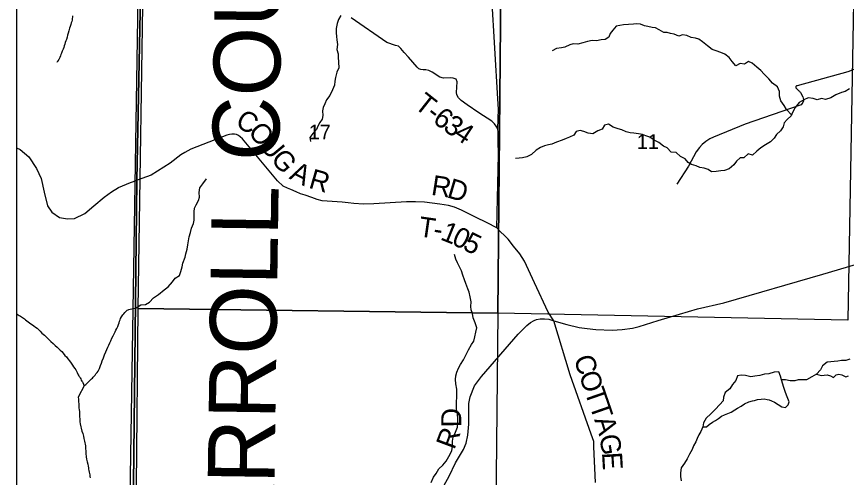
# Model space of a CAD drawing. Extents: x -1.2 to 34, y -8.5 to 22.
# Drawn here: x 2.1 to 4.454, y 18.225 to 19.531 of the extents above; entities that cross this region are included whole.
import ezdxf

# ---------------------------------------------------------------- set-up
doc = ezdxf.new("R2010")
doc.units = 0
for name, color, linetype in [('DV_X_County_Line', 7, 'Continuous'), ('GM_X_County_Road', 7, 'Continuous'), ('GM_X_County_Road_Text', 7, 'Continuous'), ('GM_X_County_Text', 7, 'Continuous'), ('GM_X_Minor_Lake', 7, 'Continuous'), ('GM_X_Minor_River', 7, 'Continuous'), ('GM_X_Section', 7, 'Continuous'), ('GM_X_Section_Text', 7, 'Continuous'), ('GM_X_Township_Road', 7, 'Continuous'), ('GM_X_Township_Road_Text', 7, 'Continuous'), ('GM_X_Unincorporated_Text', 7, 'Continuous'), ('SH_Cut_Line', 7, 'Continuous'), ('SH_Data', 7, 'Continuous')]:
    doc.layers.add(name, color=color, linetype=linetype)

msp = doc.modelspace()

# ---------------------------------------------------------------- linework, layer by layer
at = {"layer": 'DV_X_County_Line'}
msp.add_line((2.3586, 14.1), (2.465, 20.9), dxfattribs=at)
at = {"layer": 'GM_X_County_Road'}
msp.add_lwpolyline([(3.2928, 18.1676), (3.3265, 18.2291), (3.3449, 18.2664), (3.3677, 18.3046), (3.3748, 18.3225), (3.38, 18.3454), (3.3828, 18.3766), (3.3828, 18.4351), (3.3868, 18.4541), (3.3991, 18.485), (3.4183, 18.5117), (3.5231, 18.6316), (3.5436, 18.6524), (3.5469, 18.6554), (3.5577, 18.6643), (3.5681, 18.6701), (3.575, 18.6729), (3.5854, 18.6751), (3.5974, 18.6751), (3.6098, 18.6738), (3.6237, 18.6695), (3.6608, 18.6582), (3.6955, 18.6501), (3.7185, 18.6469), (3.743, 18.6441), (3.7888, 18.6427), (3.8178, 18.6443), (3.8473, 18.6482), (3.8658, 18.6531), (3.9197, 18.6699), (3.98, 18.6882), (4.0313, 18.7027), (4.1057, 18.7202), (4.3866, 18.8016), (4.7601, 18.9122)], dxfattribs=at)
at = {"layer": 'GM_X_Minor_Lake'}
for points in [[(4.463, 18.5606), (4.4524, 18.5571), (4.4395, 18.5562), (4.4293, 18.5546), (4.4187, 18.5541), (4.4092, 18.5533), (4.3989, 18.5517), (4.3861, 18.5417), (4.3801, 18.5299), (4.3684, 18.5184)], [(4.2698, 18.5016), (4.2667, 18.5118), (4.262, 18.5243), (4.2488, 18.5234), (4.234, 18.5188), (4.2218, 18.5179), (4.2082, 18.5144), (4.1938, 18.512), (4.1824, 18.51), (4.1672, 18.514), (4.1554, 18.5154), (4.1452, 18.5131), (4.1396, 18.4997), (4.1302, 18.489), (4.1227, 18.4768), (4.1102, 18.4664), (4.1054, 18.4527), (4.104, 18.4428), (4.0949, 18.4318), (4.0818, 18.418), (4.069, 18.4053), (4.0562, 18.3931), (4.0479, 18.3801), (4.0469, 18.3683)], [(4.0469, 18.3683), (4.0571, 18.3684), (4.0647, 18.3753), (4.0737, 18.3818), (4.0824, 18.3868), (4.0907, 18.3926), (4.0998, 18.3991), (4.1081, 18.403), (4.1176, 18.4061), (4.127, 18.4104), (4.1369, 18.4169), (4.1452, 18.4212), (4.155, 18.427), (4.1648, 18.4339), (4.1773, 18.4397), (4.1872, 18.4428), (4.1928, 18.4436), (4.2019, 18.446), (4.2118, 18.4472), (4.2202, 18.4476), (4.2293, 18.4462), (4.235, 18.4451), (4.2411, 18.4425), (4.2495, 18.4388), (4.2605, 18.4324), (4.2709, 18.4257), (4.2811, 18.4231), (4.2887, 18.4308), (4.2916, 18.4395), (4.2878, 18.449), (4.2839, 18.4581), (4.28, 18.4687), (4.2761, 18.48), (4.2698, 18.5016)], [(4.3684, 18.5184), (4.3822, 18.514), (4.3905, 18.5152), (4.3992, 18.5164), (4.4084, 18.5134), (4.4175, 18.5082), (4.4247, 18.5158), (4.4323, 18.5182), (4.441, 18.5164), (4.4517, 18.5104), (4.46, 18.5135)]]:
    msp.add_lwpolyline(points, dxfattribs=at)
at = {"layer": 'GM_X_Minor_River'}
for points in [[(2.2587, 19.5334), (2.2584, 19.5296), (2.2577, 19.5254), (2.2573, 19.5213), (2.2563, 19.5174), (2.2552, 19.5133), (2.2537, 19.5087), (2.2519, 19.5033), (2.2501, 19.4984), (2.2483, 19.4904), (2.2461, 19.4843), (2.2446, 19.4786), (2.2432, 19.4725), (2.2414, 19.4664), (2.2395, 19.4622), (2.2381, 19.4576), (2.2366, 19.453), (2.2352, 19.4484), (2.2337, 19.4439), (2.2319, 19.4385), (2.2297, 19.4332), (2.2271, 19.4271), (2.2256, 19.4236), (2.2246, 19.4202), (2.2227, 19.4156), (2.2198, 19.4099), (2.2172, 19.4057), (2.2157, 19.403), (2.2149, 19.403), (2.2146, 19.4011)], [(3.0198, 19.5341), (3.0135, 19.5226), (3.0095, 19.5112), (3.0066, 19.4975), (3.0064, 19.4853), (3.0076, 19.4747), (3.0085, 19.4653), (3.0098, 19.4516), (3.0084, 19.4383), (3.012, 19.4259), (3.0121, 19.416)], [(4.2984, 19.2528), (4.2837, 19.268), (4.2772, 19.2793), (4.2676, 19.2925), (4.2637, 19.3054), (4.2643, 19.3187), (4.2581, 19.3323), (4.244, 19.3424), (4.2336, 19.3544), (4.2206, 19.3676), (4.2106, 19.3781), (4.1995, 19.3879), (4.1861, 19.3996), (4.1762, 19.404), (4.1649, 19.396), (4.1519, 19.3985), (4.1402, 19.3919), (4.1295, 19.4036), (4.1214, 19.4149), (4.1092, 19.4243), (4.0977, 19.4295), (4.0844, 19.4343), (4.0726, 19.4376), (4.06, 19.4482), (4.0454, 19.4598), (4.0355, 19.4669), (4.026, 19.4703), (4.0138, 19.4717), (4.0012, 19.478), (3.9887, 19.479), (3.9781, 19.4759), (3.9651, 19.4811), (3.9552, 19.4837), (3.9453, 19.4859), (3.9358, 19.4865), (3.9228, 19.494), (3.9121, 19.4992), (3.9023, 19.5003), (3.8905, 19.5032), (3.8806, 19.5054), (3.8695, 19.5095), (3.8596, 19.5109), (3.8501, 19.5097), (3.8357, 19.5084), (3.8217, 19.5079), (3.8107, 19.5059), (3.8008, 19.5036), (3.791, 19.4929), (3.7835, 19.4829), (3.7794, 19.473), (3.7692, 19.4661), (3.7578, 19.4656), (3.745, 19.4629), (3.7328, 19.4635), (3.7192, 19.4604), (3.7059, 19.4565), (3.6915, 19.4533), (3.6789, 19.4536), (3.6691, 19.4508), (3.6551, 19.4446), (3.6452, 19.443), (3.6312, 19.4403), (3.6191, 19.4345)], [(3.0121, 19.416), (3.0127, 19.4016), (3.0136, 19.3864), (3.0084, 19.3738), (3.0044, 19.3582), (3.0023, 19.3484), (3.0017, 19.3373), (2.9958, 19.3236), (2.9884, 19.308), (2.9791, 19.295), (2.9743, 19.2843), (2.9698, 19.274), (2.9677, 19.2641), (2.969, 19.2509), (2.9665, 19.2402), (2.9601, 19.2306), (2.9546, 19.2203), (2.9505, 19.2108), (2.9404, 19.1997), (2.9315, 19.189), (2.9339, 19.1772)], [(4.4629, 19.3264), (4.45, 19.3191)], [(4.45, 19.3191), (4.4402, 19.3156), (4.4239, 19.3098), (4.4099, 19.3009), (4.3948, 19.2966), (4.3826, 19.2988), (4.3705, 19.2953), (4.3591, 19.2986), (4.3454, 19.3008), (4.3329, 19.2957), (4.3193, 19.288), (4.3088, 19.2735), (4.3009, 19.2594), (4.2972, 19.2495), (4.2855, 19.2399), (4.2772, 19.2304), (4.2739, 19.2186), (4.2668, 19.2071), (4.2551, 19.1972), (4.2491, 19.1869), (4.2382, 19.1765), (4.2246, 19.1677), (4.2114, 19.1588), (4.1997, 19.1496), (4.1876, 19.1389), (4.1751, 19.1422), (4.1626, 19.1311), (4.1528, 19.131), (4.1422, 19.1214), (4.1347, 19.1115), (4.1211, 19.1), (4.1079, 19.0953), (4.0972, 19.0941), (4.0847, 19.0925), (4.0711, 19.0912), (4.0615, 19.098), (4.0501, 19.1017), (4.0379, 19.1034), (4.028, 19.1087), (4.0147, 19.1116), (4.0051, 19.118), (3.9959, 19.1281), (3.9833, 19.1345), (3.9707, 19.1457), (3.9566, 19.1471), (3.9451, 19.1588), (3.9345, 19.1636), (3.9218, 19.1742), (3.9085, 19.1813), (3.8959, 19.1899), (3.8852, 19.1936), (3.8757, 19.1969), (3.8635, 19.1987), (3.8506, 19.2005), (3.8403, 19.2019), (3.8293, 19.2048), (3.8167, 19.2101), (3.8064, 19.213), (3.7923, 19.2178), (3.7786, 19.226), (3.7672, 19.2237), (3.7612, 19.2118), (3.7483, 19.2079), (3.7344, 19.1991), (3.7214, 19.2009), (3.7092, 19.2057), (3.6986, 19.2083), (3.6868, 19.2051), (3.6808, 19.1952), (3.6687, 19.1894), (3.6589, 19.1855), (3.6472, 19.1813), (3.6316, 19.1751), (3.6184, 19.17), (3.6089, 19.168), (3.5975, 19.1653), (3.5858, 19.1602), (3.5733, 19.1529), (3.5605, 19.1403), (3.5473, 19.1337), (3.5348, 19.1313), (3.5253, 19.1301), (3.515, 19.1289)], [(2.4391, 18.7059), (2.4521, 18.7144), (2.4654, 18.7157), (2.4767, 18.7219), (2.4882, 18.7338), (2.5025, 18.7438), (2.5186, 18.7569), (2.5299, 18.7658), (2.5422, 18.7796), (2.5497, 18.7895), (2.5617, 18.7976), (2.5657, 18.8087), (2.5697, 18.822), (2.5719, 18.8327), (2.5785, 18.8491), (2.5799, 18.8586), (2.5839, 18.8723), (2.5857, 18.8844), (2.5874, 18.8958), (2.5896, 18.9069), (2.5932, 18.9198), (2.5957, 18.9316), (2.6013, 18.9446), (2.6034, 18.9545), (2.6032, 18.978), (2.6046, 18.9882), (2.6097, 18.9978), (2.6157, 19.01), (2.6186, 19.0195), (2.618, 19.0328), (2.6198, 19.0457), (2.6284, 19.0572), (2.6384, 19.071)], [(3.2755, 18.2112), (3.2829, 18.2261), (3.29, 18.2368), (3.2974, 18.2494), (3.3094, 18.2602), (3.3187, 18.2713), (3.3258, 18.2843), (3.3343, 18.3007), (3.336, 18.314), (3.3366, 18.3281), (3.3384, 18.3395), (3.3451, 18.3532), (3.3502, 18.3677), (3.3516, 18.3791), (3.3518, 18.3901), (3.3505, 18.4057), (3.3481, 18.4186), (3.348, 18.4284), (3.3482, 18.4413), (3.3485, 18.4508), (3.3491, 18.4611), (3.349, 18.4751), (3.3458, 18.491), (3.3449, 18.5024), (3.3459, 18.513), (3.3484, 18.5237), (3.3532, 18.5351), (3.3588, 18.5458), (3.3674, 18.5585), (3.3755, 18.5737), (3.3814, 18.5871), (3.3903, 18.6016), (3.397, 18.6112), (3.3995, 18.6241), (3.4024, 18.6367), (3.4053, 18.6488), (3.4006, 18.6632), (3.3951, 18.678), (3.3931, 18.6901), (3.3896, 18.6999), (3.3887, 18.7094), (3.3897, 18.723), (3.3869, 18.7374), (3.3834, 18.7499), (3.3795, 18.7601), (3.3744, 18.7745), (3.3709, 18.7851), (3.3658, 18.7987), (3.3615, 18.8104), (3.3576, 18.8202), (3.3506, 18.8334), (3.346, 18.844), (3.3417, 18.8568)], [(2.1, 18.689), (2.1016, 18.6881), (2.1046, 18.6859), (2.1077, 18.684), (2.1111, 18.6821), (2.1138, 18.6803), (2.1169, 18.6784), (2.1196, 18.6769), (2.1223, 18.6747), (2.1257, 18.6717), (2.1292, 18.6687), (2.1326, 18.6661), (2.1365, 18.6631), (2.1487, 18.6545), (2.1533, 18.6515), (2.1579, 18.6481), (2.1621, 18.6444), (2.1667, 18.6399), (2.1714, 18.6343), (2.1787, 18.6287), (2.1848, 18.6226), (2.1914, 18.6163), (2.1975, 18.6106), (2.2037, 18.605), (2.2098, 18.5994), (2.2148, 18.5945), (2.2194, 18.59), (2.2236, 18.5863), (2.2279, 18.5821), (2.2317, 18.5776), (2.2371, 18.5712), (2.2414, 18.5667), (2.2452, 18.5611), (2.2499, 18.5554), (2.2545, 18.5494), (2.2584, 18.5438), (2.2618, 18.5389), (2.2649, 18.5344), (2.2677, 18.5302), (2.27, 18.5264), (2.2719, 18.5223), (2.2735, 18.5181), (2.2751, 18.5159), (2.2766, 18.5136), (2.2778, 18.5117), (2.2789, 18.5098), (2.2801, 18.5076), (2.282, 18.5045), (2.2836, 18.5011), (2.2852, 18.4985), (2.2867, 18.4959), (2.2879, 18.494), (2.2898, 18.4898)], [(2.2898, 18.4898), (2.291, 18.4872), (2.2933, 18.4864), (2.2963, 18.4888), (2.2997, 18.4926), (2.3128, 18.5049), (2.3154, 18.5069), (2.3173, 18.5092), (2.3199, 18.5122), (2.3225, 18.5153), (2.3251, 18.5188), (2.3281, 18.5226), (2.3311, 18.5264), (2.3333, 18.5303), (2.3355, 18.5341), (2.3377, 18.5421), (2.3407, 18.549), (2.3428, 18.5555), (2.3461, 18.5643), (2.3498, 18.573), (2.3531, 18.5811), (2.3561, 18.5883), (2.359, 18.5944), (2.3616, 18.6002), (2.3646, 18.6063), (2.3675, 18.6128), (2.3704, 18.6204), (2.3742, 18.6262), (2.3771, 18.6319), (2.3797, 18.6376), (2.3819, 18.643), (2.3841, 18.6476), (2.3867, 18.6533), (2.3889, 18.6587), (2.3908, 18.6632), (2.3918, 18.6682), (2.3933, 18.672), (2.3948, 18.6754), (2.3974, 18.68), (2.3992, 18.6835), (2.4014, 18.6865), (2.4037, 18.6892), (2.4071, 18.6931), (2.4097, 18.6954), (2.4119, 18.6973), (2.4138, 18.6989), (2.4164, 18.7), (2.4187, 18.7012), (2.4391, 18.7059)], [(4.463, 18.5606), (4.4524, 18.5571), (4.4395, 18.5562), (4.4293, 18.5546), (4.4187, 18.5541), (4.4092, 18.5533), (4.3989, 18.5517), (4.3861, 18.5417), (4.3801, 18.5299), (4.3684, 18.5184), (4.3556, 18.5107), (4.3401, 18.5018), (4.3169, 18.5016), (4.3075, 18.4993), (4.2942, 18.4992), (4.2812, 18.5017), (4.2698, 18.5016), (4.2667, 18.5118), (4.262, 18.5243), (4.2488, 18.5234), (4.234, 18.5188), (4.2218, 18.5179), (4.2082, 18.5144), (4.1938, 18.512), (4.1824, 18.51), (4.1672, 18.514), (4.1554, 18.5154), (4.1452, 18.5131), (4.1396, 18.4997), (4.1302, 18.489), (4.1227, 18.4768), (4.1102, 18.4664), (4.1054, 18.4527), (4.104, 18.4428), (4.0949, 18.4318), (4.0818, 18.418), (4.069, 18.4053), (4.0562, 18.3931), (4.0479, 18.3801), (4.0469, 18.3683), (4.0409, 18.3554), (4.0353, 18.3458), (4.0308, 18.3355), (4.0267, 18.326), (4.02, 18.3146), (4.0159, 18.3043), (4.0088, 18.2909), (4.0024, 18.2776), (3.9942, 18.2661), (3.9852, 18.2524), (3.983, 18.2383), (3.9831, 18.2284), (3.9847, 18.2155)], [(2.2926, 18.4867), (2.2748, 18.4524), (2.2752, 18.4467), (2.2757, 18.4399), (2.2761, 18.4338), (2.2766, 18.4277), (2.277, 18.4228), (2.2779, 18.4171), (2.2783, 18.4118), (2.2784, 18.4053), (2.2785, 18.3973), (2.279, 18.3916), (2.279, 18.3871), (2.2795, 18.3825), (2.2803, 18.3768), (2.2855, 18.3564), (2.2875, 18.3496), (2.2895, 18.3427), (2.2911, 18.3359), (2.2923, 18.3283), (2.2939, 18.3238), (2.2947, 18.3192), (2.2952, 18.3151), (2.2956, 18.3101), (2.2957, 18.3056), (2.2961, 18.3014), (2.2965, 18.2976), (2.2966, 18.293), (2.2971, 18.2835), (2.2983, 18.2775), (2.3, 18.2691), (2.3016, 18.2627), (2.3028, 18.2574), (2.3036, 18.2528), (2.3044, 18.249), (2.3052, 18.2445), (2.306, 18.2403), (2.3068, 18.2362), (2.3073, 18.2324), (2.3081, 18.2278), (2.3085, 18.224)]]:
    msp.add_lwpolyline(points, dxfattribs=at)
at = {"layer": 'GM_X_Section'}
for points in [[(2.4611, 19.7462), (3.4745, 19.7148), (3.4647, 18.6909), (2.4444, 18.7044)], [(3.4745, 19.7148), (4.4756, 19.6778), (4.4573, 18.6708), (3.4647, 18.6909)], [(3.4647, 18.6909), (3.4549, 17.6781), (2.4351, 17.6992), (2.4444, 18.7044)]]:
    msp.add_lwpolyline(points, close=True, dxfattribs=at)
at = {"layer": 'GM_X_Township_Road'}
msp.add_line((3.4653, 19.298), (3.4459, 19.6223), dxfattribs=at)
for points in [[(3.3309, 19.3575), (3.3108, 19.3568), (3.3009, 19.3599), (3.2787, 19.3734), (3.269, 19.3786), (3.2604, 19.3805), (3.2528, 19.3807), (3.2462, 19.3812), (3.2405, 19.3834), (3.2365, 19.3876), (3.2116, 19.4159), (3.1992, 19.4292), (3.1897, 19.4409), (3.183, 19.4472), (3.175, 19.4489), (3.15, 19.4581), (3.049, 19.5273)], [(4.716, 19.4732), (4.7006, 19.4578), (4.6946, 19.4521), (4.6853, 19.447), (4.6746, 19.4437), (4.6621, 19.4395), (4.6417, 19.4335), (4.5125, 19.4047), (4.5004, 19.3961), (4.4749, 19.381), (4.4577, 19.3749), (4.3137, 19.3354), (4.3119, 19.3347), (4.3112, 19.3343), (4.3106, 19.3335), (4.3101, 19.3325), (4.31, 19.3309), (4.3105, 19.3297), (4.3115, 19.3285), (4.3192, 19.3211), (4.3205, 19.3196)], [(3.4652, 19.2132), (3.4599, 19.2204), (3.4553, 19.2275), (3.448, 19.2347), (3.4107, 19.2586), (3.3784, 19.2809), (3.3607, 19.2932), (3.353, 19.3014), (3.3488, 19.3097), (3.3476, 19.3163), (3.3493, 19.3466), (3.3469, 19.3536), (3.3387, 19.3565), (3.3309, 19.3575)], [(4.3205, 19.3196), (4.3217, 19.318), (4.3231, 19.3156), (4.3302, 19.3034), (4.3313, 19.3003), (4.3322, 19.2966), (4.3317, 19.2927), (4.3297, 19.2878), (4.3276, 19.2842), (4.3252, 19.2814), (4.3226, 19.2797), (4.1662, 19.226), (4.077, 19.1899), (4.066, 19.1848), (4.0551, 19.1773), (4.045, 19.1687), (4.0369, 19.16), (4.0274, 19.1476), (4.0056, 19.1077), (3.9725, 19.0559)], [(3.7419, 18.2108), (3.7375, 18.3122), (3.7372, 18.3239), (3.7368, 18.327), (3.7296, 18.3482), (3.6699, 18.5164), (3.6237, 18.6695), (3.608, 18.6934), (3.5693, 18.7765), (3.5404, 18.8385), (3.5272, 18.8593), (3.5097, 18.8809), (3.494, 18.9), (3.4826, 18.9116), (3.4736, 18.9206), (3.4619, 18.9326), (3.4667, 19.1403), (3.4661, 19.1781), (3.4658, 19.1896), (3.4656, 19.2035), (3.4652, 19.2132), (3.467, 19.2692), (3.4653, 19.298)], [(3.4619, 18.9326), (3.4345, 18.9466), (3.4015, 18.963), (3.3616, 18.9825), (3.3418, 18.9916), (3.3252, 18.9962), (3.3004, 18.9997), (3.2567, 19.0056), (3.231, 19.0065), (3.2055, 19.0067), (3.1133, 19.0002), (3.0841, 19), (3.0564, 19.0018), (3.0407, 19.003), (3.0232, 19.0049), (2.9667, 19.0091), (2.9524, 19.0132), (2.9373, 19.0183), (2.9182, 19.0247), (2.9052, 19.0289), (2.8932, 19.0345), (2.8781, 19.0411), (2.8682, 19.0454), (2.8564, 19.0507), (2.8402, 19.0657), (2.741, 19.1845), (2.734, 19.1905), (2.7294, 19.1942), (2.7235, 19.1972), (2.7176, 19.1984), (2.7103, 19.1982), (2.7036, 19.1973), (2.6963, 19.1948), (2.5944, 19.1554), (2.5771, 19.1464), (2.5656, 19.139), (2.5358, 19.116), (2.4818, 19.0815), (2.4416, 19.0672)], [(2.1, 19.1588), (2.1105, 19.1544), (2.135, 19.134), (2.1568, 19.1008), (2.1696, 19.072), (2.1782, 19.034), (2.1876, 18.9946), (2.2003, 18.9768), (2.2213, 18.9622), (2.2448, 18.9578), (2.2642, 18.9591), (2.2933, 18.9734), (2.3189, 18.9945), (2.348, 19.0194), (2.3695, 19.0348), (2.3887, 19.0467), (2.4232, 19.0606), (2.4416, 19.0672)]]:
    msp.add_lwpolyline(points, dxfattribs=at)
at = {"layer": 'GM_X_Unincorporated_Text'}
for p, q in [((2.1, 20.6871), (2.1, 14.6393)), ((2.4414, 19.0677), (2.4628, 20.1657)), ((2.4258, 17.6899), (2.4414, 19.0677))]:
    msp.add_line(p, q, dxfattribs=at)
msp.add_lwpolyline([(8.4143, 20.9), (2.465, 20.9), (2.4644, 20.6742), (2.4628, 20.1657), (2.4414, 19.0677), (2.4258, 17.6899), (2.8968, 17.6806), (3.3984, 17.6707), (4.1759, 17.654), (4.4093, 17.6489), (4.6867, 17.6371)], dxfattribs=at)
at = {"layer": 'SH_Cut_Line'}
msp.add_lwpolyline([(2.465, 20.9), (2.1, 20.9), (2.1, 14.1), (2.3586, 14.1), (2.3643, 14.4203), (2.3672, 14.6322), (2.3867, 15.3183), (2.402, 16.1209), (2.4189, 17.3824), (2.4258, 17.6899), (2.4414, 19.0677), (2.4628, 20.1657), (2.4644, 20.6742)], close=True, dxfattribs=at)
msp.add_lwpolyline([(8.9, 20.9), (2.465, 20.9), (2.4644, 20.6742), (2.4628, 20.1657), (2.4414, 19.0677), (2.4258, 17.6899), (2.8968, 17.6806), (3.3984, 17.6707), (4.1759, 17.654), (4.4093, 17.6489), (4.6867, 17.6371)], dxfattribs=at)
at = {"layer": 'SH_Data'}
msp.add_line((2.1, 20.9), (2.1, 14.1), dxfattribs=at)
msp.add_line((2.1, 20.9), (2.1, 14.1), dxfattribs=at)

# ---------------------------------------------------------------- texts
at = {"layer": 'GM_X_County_Road_Text'}
for s, rotation, p in [('D', 90.5481, (3.3615, 18.3674)), ('R', 69.5522, (3.3413, 18.3018))]:
    msp.add_text(s, height=0.0568, rotation=rotation, dxfattribs=at).set_placement(p)
at = {"layer": 'GM_X_County_Text'}
msp.add_text('CARROLL COUNTY', height=0.189394, rotation=89.1839, dxfattribs=at).set_placement((2.8263, 17.8542))
at = {"layer": 'GM_X_Section_Text'}
for s, p in [('17', (2.9289, 19.1831)), ('11', (3.8593, 19.1559))]:
    msp.add_text(s, height=0.04186, rotation=0, dxfattribs=at).set_placement(p)
at = {"layer": 'GM_X_Township_Road_Text'}
for s, rotation, p in [('T', 321.7491, (3.2249, 19.2751)), ('C', 330.8883, (2.7173, 19.2221)), ('-', 321.9139, (3.2584, 19.2487)), ('6', 322.525, (3.2773, 19.2339)), ('3', 324.5039, (3.3068, 19.2113)), ('O', 310.5005, (2.754, 19.2028)), ('4', 326.5402, (3.3371, 19.1897)), ('U', 309.9707, (2.7864, 19.1649)), ('G', 310.1532, (2.8186, 19.1264)), ('A', 333.7031, (2.8708, 19.0726)), ('R', 343.7589, (2.9258, 19.0465)), ('R', 351.0709, (3.2739, 19.0264)), ('D', 343.5024, (3.3181, 19.0196)), ('T', 351.8296, (3.2377, 18.9089)), ('-', 351.6337, (3.2797, 18.9028)), ('1', 337.9358, (3.2993, 18.9004)), ('0', 334.3636, (3.3309, 18.8876)), ('5', 334.2833, (3.3624, 18.8725)), ('C', 286.7735, (3.68, 18.5635)), ('O', 288.7053, (3.6942, 18.5168)), ('T', 289.102, (3.7103, 18.469)), ('T', 289.1011, (3.7242, 18.4289)), ('A', 287.4097, (3.738, 18.3891)), ('G', 279.2159, (3.7525, 18.3435)), ('E', 273.3511, (3.7603, 18.2957))]:
    msp.add_text(s, height=0.0568, rotation=rotation, dxfattribs=at).set_placement(p)

doc.saveas('drawing.dxf')
